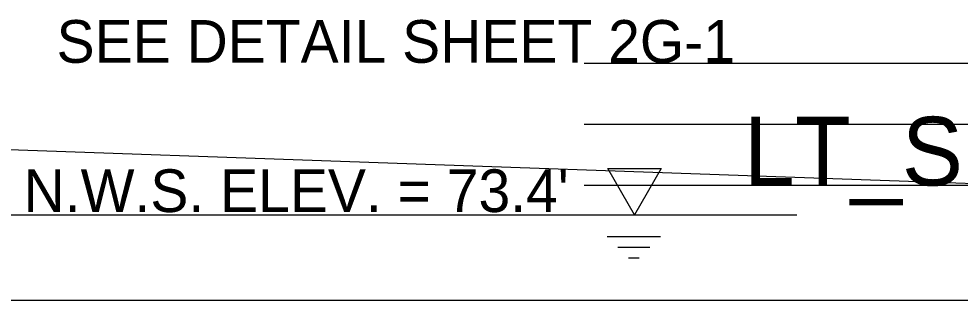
# Model space of a CAD drawing. Extents: x -14026 to 1303, y -10 to 9533.
# Drawn here: x 96.33 to 111.77, y 5000 to 5004.61 of the extents above; entities that cross this region are included whole.
import ezdxf

# ---------------------------------------------------------------- set-up
doc = ezdxf.new("R2010")
doc.units = 0
for name, color, linetype in [('Exist Cross Section Cell', 7, 'Continuous'), ('Exist XS Ground Line', 7, 'Continuous'), ('Old_Level_10', 7, 'Continuous'), ('Prop XS Side Slope Text', 7, 'Continuous'), ('Scratch_Level_0', 7, 'Continuous'), ('Scratch_Level_1', 7, 'Continuous'), ('Scratch_Level_3', 7, 'Continuous')]:
    doc.layers.add(name, color=color, linetype=linetype)

msp = doc.modelspace()

# ---------------------------------------------------------------- linework, layer by layer
at = {"layer": 'Exist Cross Section Cell'}
msp.add_line((0, 5000), (150, 5000), dxfattribs=at)
at = {"layer": 'Exist XS Ground Line'}
msp.add_lwpolyline([(74.654, 5002.365), (84.122, 5002.607), (86.233, 5002.67), (87.741, 5002.66), (94.101, 5002.493), (95.538, 5002.49), (121.648, 5001.571), (124.073, 5001.478), (124.8, 5001.452), (125.798, 5002.067), (129.983, 5004.611)], dxfattribs=at)
at = {"layer": 'Prop XS Side Slope Text'}
for p, q in [((105.98, 5001.046), (106.855, 5001.046)), ((106.155, 5000.871), (106.68, 5000.871)), ((106.33, 5000.696), (106.505, 5000.696))]:
    msp.add_line(p, q, dxfattribs=at)
msp.add_lwpolyline([(105.993, 5002.159), (106.868, 5002.159), (106.431, 5001.4)], close=True, dxfattribs=at)
at = {"layer": 'Scratch_Level_1'}
msp.add_line((87.209, 5001.4), (109.095, 5001.4), dxfattribs=at)
at = {"layer": 'Scratch_Level_3'}
for p, q in [((128.78, 5003.88), (105.602, 5003.88)), ((115.868, 5002.88), (105.602, 5002.88)), ((112.865, 5001.88), (105.602, 5001.88))]:
    msp.add_line(p, q, dxfattribs=at)

# ---------------------------------------------------------------- texts
at = {"layer": 'Old_Level_10'}
msp.add_text('SEE DETAIL SHEET 2G-1', height=0.7, dxfattribs=at).set_placement((96.947, 5003.891))
at = {"layer": 'Prop XS Side Slope Text'}
msp.add_text("N.W.S. ELEV. = 73.4'", height=0.7, dxfattribs=at).set_placement((96.406, 5001.444))
at = {"layer": 'Scratch_Level_0'}
msp.add_text('LT_Slope_Fill', height=1.125, dxfattribs=at).set_placement((108.225, 5001.88))

doc.saveas('drawing.dxf')
